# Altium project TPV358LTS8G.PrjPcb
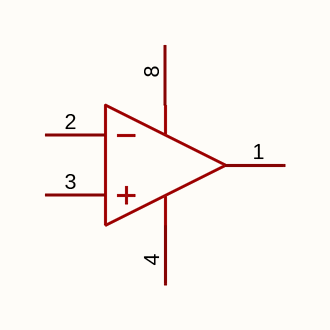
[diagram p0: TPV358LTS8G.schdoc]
1 sheet, 1 parts. Net scope: global (net labels, ports and power ports of the same name join across sheets).

## Sheet TPV358LTS8G.schdoc
size 127 x 101 mm

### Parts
U?  tpv358lts8g  [TSSOP-8_L4.4-W3.0-P0.65-LS6.4-BL]  (value not drawn)  (part A of 2)

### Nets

Not connected (* = marked no-connect by the designer): U? 1(OUT_A) 2(IN_A-) 3(IN_A+) 4(V-) 8(V+)

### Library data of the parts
U? = tpv358lts8g: 放大器数:2;轨到轨:轨到轨输入,轨到轨输出;增益带宽积(GBW):1MHz;输入失调电压(Vos):500uV;压摆率(SR):-;输入偏置电流(Ib):10pA;; Manufacturer: TECH PUBLIC(台舟); AddInBom: yes; ModelId: 85577802f9634e7e85ffa2fd25a37b6f; ModelName: TSSOP-8_L4.4-W3.0-P0.65-LS6.4-BL-2; ModelTransform: 118.11,251.968,0,0,0,0,0,0,0; Number of Channels: 2; Gain Bandwidth Product: 1MHz; Vos - Input Offset Voltage: 500uV; Input Offset Voltage Drift(Vos TC): 650nV/℃; Ib - Input Bias Current: 10pA; Common Mode Rejection Ratio(CMRR): 95dB; Quiescent Current: 50uA; Output Current: 20mA; Single supply: 2.1V~5.5V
